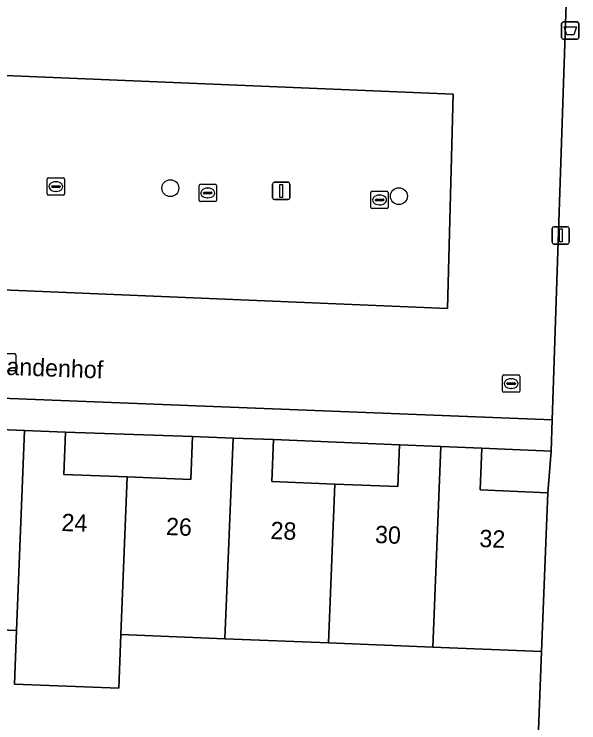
# Model space of a CAD drawing. Extents: x 160786 to 161429, y 386828 to 387485.
# Drawn here: x 161067.25 to 161099.81, y 387170.31 to 387211.19 of the extents above; entities that cross this region are included whole.
import ezdxf

# ---------------------------------------------------------------- set-up
doc = ezdxf.new("R2010")
doc.units = 0
for name, color, linetype in [('IMGEO_Afvalbak', 7, 'Continuous'), ('IMGEO_Boom', 7, 'Continuous'), ('IMGEO_Erf', 7, 'Continuous'), ('IMGEO_Kolk', 7, 'Continuous'), ('IMGEO_Lichtmast', 7, 'Continuous'), ('IMGEO_Openbare_ruimte_label', 7, 'Continuous'), ('IMGEO_Pand', 7, 'Continuous'), ('IMGEO_Pand_nummerreeks', 7, 'Continuous'), ('IMGEO_Parkeervlak_open', 7, 'Continuous'), ('IMGEO_Rijbaan_lokaal_open', 7, 'Continuous'), ('IMGEO_Rioolput', 7, 'Continuous'), ('IMGEO_Voetpad_open', 7, 'Continuous')]:
    doc.layers.add(name, color=color, linetype=linetype)

msp = doc.modelspace()

# ---------------------------------------------------------------- linework, layer by layer
at = {"layer": 'IMGEO_Afvalbak'}
for p, q in [((161098.821, 387209.849), (161098.821, 387210.649)), ((161098.821, 387210.649), (161098.821, 387209.849)), ((161098.921, 387210.749), (161099.711, 387210.749)), ((161099.711, 387210.749), (161098.921, 387210.749)), ((161099.811, 387210.649), (161099.811, 387209.849)), ((161099.811, 387209.849), (161099.811, 387210.649)), ((161099.711, 387209.749), (161098.921, 387209.749)), ((161098.921, 387209.749), (161099.711, 387209.749))]:
    msp.add_line(p, q, dxfattribs=at)
msp.add_lwpolyline([(161098.964, 387210.463), (161099.668, 387210.463), (161099.519, 387209.993), (161099.113, 387209.993), (161098.964, 387210.463)], dxfattribs=at)
for centre, start, end in [((161098.921, 387210.649), 90, 180), ((161098.921, 387210.649), 90, 180), ((161099.711, 387210.649), 0, 90), ((161099.711, 387210.649), 360, 90), ((161098.921, 387209.849), 180, 270), ((161098.921, 387209.849), 180, 270), ((161099.711, 387209.849), 270, 0), ((161099.711, 387209.849), 270, 0)]:
    msp.add_arc(centre, 0.1, start, end, dxfattribs=at)
at = {"layer": 'IMGEO_Boom'}
for centre in [(161076.258, 387201.154), (161089.435, 387200.693)]:
    msp.add_circle(centre, 0.489, dxfattribs=at)
at = {"layer": 'IMGEO_Erf'}
for points in [[(161070.215, 387187.083), (161070.116, 387184.642), (161073.775, 387184.495), (161077.435, 387184.347), (161077.536, 387186.834)], [(161082.211, 387186.646), (161082.113, 387184.227), (161085.748, 387184.08), (161089.381, 387183.934), (161089.478, 387186.343)], [(161094.224, 387186.152), (161094.127, 387183.743), (161098.029, 387183.585), (161098.215, 387185.98)]]:
    msp.add_lwpolyline(points, close=True, dxfattribs=at)
msp.add_lwpolyline([(161097.233, 387163.345), (161097.659, 387174.419), (161091.385, 387174.672), (161085.378, 387174.915), (161079.404, 387175.156), (161073.408, 387175.398), (161073.283, 387172.301), (161067.264, 387172.544), (161067.389, 387175.64), (161061.396, 387175.882), (161055.397, 387176.124), (161049.305, 387176.37), (161043.243, 387176.615), (161042.991, 387170.375), (161039.859, 387170.501), (161040.111, 387176.741), (161037.169, 387176.86), (161031.147, 387177.103), (161025.183, 387177.344), (161019.173, 387177.586), (161013.147, 387177.829), (161007.179, 387178.07), (161001.282, 387178.308), (161000.924, 387167.442)], dxfattribs=at)
at = {"layer": 'IMGEO_Kolk'}
for p, q in [((161069.16, 387200.818), (161069.16, 387201.67)), ((161069.235, 387201.744), (161070.087, 387201.744)), ((161069.648, 387201.524), (161069.673, 387201.524)), ((161070.161, 387201.67), (161070.161, 387200.818)), ((161069.419, 387201.238), (161069.419, 387201.25)), ((161069.857, 387201.201), (161069.459, 387201.201)), ((161069.462, 387201.287), (161069.86, 387201.287)), ((161069.903, 387201.25), (161069.903, 387201.238)), ((161077.913, 387200.451), (161077.913, 387201.303)), ((161077.988, 387201.377), (161078.84, 387201.377)), ((161078.401, 387201.157), (161078.426, 387201.157)), ((161078.914, 387201.303), (161078.914, 387200.451)), ((161070.087, 387200.744), (161069.235, 387200.744)), ((161069.671, 387200.964), (161069.646, 387200.964)), ((161078.172, 387200.871), (161078.172, 387200.883)), ((161078.61, 387200.834), (161078.212, 387200.834)), ((161078.215, 387200.92), (161078.613, 387200.92)), ((161078.656, 387200.883), (161078.656, 387200.871)), ((161087.824, 387200.046), (161087.824, 387200.898)), ((161087.899, 387200.972), (161088.751, 387200.972)), ((161088.312, 387200.752), (161088.337, 387200.752)), ((161088.825, 387200.898), (161088.825, 387200.046)), ((161078.84, 387200.377), (161077.988, 387200.377)), ((161078.424, 387200.597), (161078.399, 387200.597)), ((161088.083, 387200.466), (161088.083, 387200.478)), ((161088.521, 387200.429), (161088.123, 387200.429)), ((161088.126, 387200.515), (161088.524, 387200.515)), ((161088.567, 387200.478), (161088.567, 387200.466)), ((161088.751, 387199.972), (161087.899, 387199.972)), ((161088.335, 387200.192), (161088.31, 387200.192))]:
    msp.add_line(p, q, dxfattribs=at)
for points in [[(161069.16, 387200.818), (161069.16, 387201.67)], [(161069.235, 387201.744), (161070.087, 387201.744)], [(161070.161, 387201.67), (161070.161, 387200.818)], [(161077.913, 387200.451), (161077.913, 387201.303)], [(161077.988, 387201.377), (161078.84, 387201.377)], [(161078.914, 387201.303), (161078.914, 387200.451)], [(161070.087, 387200.744), (161069.235, 387200.744)], [(161087.824, 387200.046), (161087.824, 387200.898)], [(161087.899, 387200.972), (161088.751, 387200.972)], [(161088.825, 387200.898), (161088.825, 387200.046)], [(161078.84, 387200.377), (161077.988, 387200.377)], [(161088.751, 387199.972), (161087.899, 387199.972)]]:
    msp.add_lwpolyline(points, dxfattribs=at)
for centre, radius, start, end in [((161069.237, 387201.668), 0.0765, 91.552, 178.448), ((161069.237, 387201.668), 0.0765, 91.552, 178.448), ((161070.085, 387201.668), 0.0765, 1.552, 88.448), ((161070.085, 387201.668), 0.0765, 1.552, 88.448), ((161069.459, 387201.247), 0.0403, 85.8775, 175.7526), ((161069.456, 387201.237), 0.0366, 178.938, 274.7102), ((161069.86, 387201.244), 0.043, 264.8664, 352.4533), ((161069.864, 387201.249), 0.0386, 1.7309, 96.639), ((161077.99, 387201.301), 0.0765, 91.552, 178.448), ((161077.99, 387201.301), 0.0765, 91.552, 178.448), ((161078.838, 387201.301), 0.0765, 1.552, 88.448), ((161078.838, 387201.301), 0.0765, 1.552, 88.448), ((161069.237, 387200.82), 0.0765, 181.552, 268.448), ((161069.237, 387200.82), 0.0765, 181.552, 268.448), ((161070.085, 387200.82), 0.0765, 271.552, 358.448), ((161070.085, 387200.82), 0.0765, 271.552, 358.448), ((161078.212, 387200.88), 0.0403, 85.8775, 175.7526), ((161078.209, 387200.87), 0.0366, 178.938, 274.7102), ((161078.613, 387200.877), 0.043, 264.8664, 352.4533), ((161078.617, 387200.882), 0.0386, 1.7309, 96.639), ((161087.901, 387200.896), 0.0765, 91.552, 178.448), ((161087.901, 387200.896), 0.0765, 91.552, 178.448), ((161088.749, 387200.896), 0.0765, 1.552, 88.448), ((161088.749, 387200.896), 0.0765, 1.552, 88.448), ((161077.99, 387200.453), 0.0765, 181.552, 268.448), ((161077.99, 387200.453), 0.0765, 181.552, 268.448), ((161078.838, 387200.453), 0.0765, 271.552, 358.448), ((161078.838, 387200.453), 0.0765, 271.552, 358.448), ((161088.123, 387200.475), 0.0403, 85.8775, 175.7526), ((161088.12, 387200.465), 0.0366, 178.938, 274.7102), ((161088.524, 387200.472), 0.043, 264.8664, 352.4533), ((161088.528, 387200.477), 0.0386, 1.7309, 96.639), ((161087.901, 387200.048), 0.0765, 181.552, 268.448), ((161087.901, 387200.048), 0.0765, 181.552, 268.448), ((161088.749, 387200.048), 0.0765, 271.552, 358.448), ((161088.749, 387200.048), 0.0765, 271.552, 358.448)]:
    msp.add_arc(centre, radius, start, end, dxfattribs=at)
for centre, major_axis, ratio, start_param, end_param in [((161069.647, 387201.244), (-0.387, 0.002), 0.722429, 4.712389, 7.853982), ((161069.672, 387201.244), (-0.39, 0.002), 0.717154, 1.570796, 4.712389), ((161078.4, 387200.877), (-0.387, 0.002), 0.722429, 4.712389, 7.853982), ((161078.425, 387200.877), (-0.39, 0.002), 0.717154, 1.570796, 4.712389), ((161088.311, 387200.472), (-0.387, 0.002), 0.722429, 4.712389, 7.853982), ((161088.336, 387200.472), (-0.39, 0.002), 0.717154, 1.570796, 4.712389)]:
    msp.add_ellipse(centre, major_axis=major_axis, ratio=ratio, start_param=start_param, end_param=end_param, dxfattribs=at)
at = {"layer": 'IMGEO_Lichtmast'}
for p, q in [((161082.157, 387200.594), (161082.157, 387201.394)), ((161082.157, 387201.394), (161082.157, 387200.594)), ((161082.257, 387201.494), (161083.047, 387201.494)), ((161083.047, 387201.494), (161082.257, 387201.494)), ((161083.147, 387201.394), (161083.147, 387200.594)), ((161083.147, 387200.594), (161083.147, 387201.394)), ((161083.047, 387200.494), (161082.257, 387200.494)), ((161082.257, 387200.494), (161083.047, 387200.494)), ((161098.272, 387198.03), (161098.272, 387198.83)), ((161098.272, 387198.83), (161098.272, 387198.03)), ((161098.372, 387198.93), (161099.162, 387198.93)), ((161099.162, 387198.93), (161098.372, 387198.93)), ((161099.262, 387198.83), (161099.262, 387198.03)), ((161099.262, 387198.03), (161099.262, 387198.83)), ((161099.162, 387197.93), (161098.372, 387197.93)), ((161098.372, 387197.93), (161099.162, 387197.93))]:
    msp.add_line(p, q, dxfattribs=at)
for points in [[(161082.577, 387201.369), (161082.727, 387201.369), (161082.727, 387200.619), (161082.577, 387200.619), (161082.577, 387201.369)], [(161098.692, 387198.805), (161098.842, 387198.805), (161098.842, 387198.055), (161098.692, 387198.055), (161098.692, 387198.805)]]:
    msp.add_lwpolyline(points, dxfattribs=at)
for centre, start, end in [((161082.257, 387201.394), 90, 180), ((161082.257, 387201.394), 90, 180), ((161083.047, 387201.394), 0, 90), ((161083.047, 387201.394), 360, 90), ((161082.257, 387200.594), 180, 270), ((161082.257, 387200.594), 180, 270), ((161083.047, 387200.594), 270, 0), ((161083.047, 387200.594), 270, 0), ((161098.372, 387198.83), 90, 180), ((161098.372, 387198.83), 90, 180), ((161099.162, 387198.83), 0, 90), ((161099.162, 387198.83), 360, 90), ((161098.372, 387198.03), 180, 270), ((161098.372, 387198.03), 180, 270), ((161099.162, 387198.03), 270, 0), ((161099.162, 387198.03), 270, 0)]:
    msp.add_arc(centre, 0.1, start, end, dxfattribs=at)
at = {"layer": 'IMGEO_Pand'}
for points in [[(161065.496, 387187.273), (161065.397, 387184.815), (161061.762, 387184.962), (161061.396, 387175.882), (161067.389, 387175.64), (161067.855, 387187.178)], [(161073.775, 387184.495), (161070.116, 387184.642), (161070.215, 387187.083), (161067.855, 387187.178), (161067.389, 387175.64), (161067.264, 387172.544), (161073.283, 387172.301), (161073.408, 387175.398)], [(161077.536, 387186.834), (161077.435, 387184.347), (161073.775, 387184.495), (161073.408, 387175.398), (161079.404, 387175.156), (161079.872, 387186.74)], [(161079.872, 387186.74), (161079.404, 387175.156), (161085.378, 387174.915), (161085.748, 387184.08), (161082.113, 387184.227), (161082.211, 387186.646)], [(161089.478, 387186.343), (161089.381, 387183.934), (161085.748, 387184.08), (161085.378, 387174.915), (161091.385, 387174.672), (161091.852, 387186.247)], [(161091.852, 387186.247), (161091.385, 387174.672), (161097.659, 387174.419), (161098.029, 387183.585), (161094.127, 387183.743), (161094.224, 387186.152)]]:
    msp.add_lwpolyline(points, close=True, dxfattribs=at)
at = {"layer": 'IMGEO_Parkeervlak_open'}
msp.add_lwpolyline([(161092.567, 387206.57), (161045.954, 387208.523), (161045.642, 387208.536), (161045.124, 387196.181), (161045.495, 387196.166), (161092.237, 387194.215)], close=True, dxfattribs=at)
at = {"layer": 'IMGEO_Rijbaan_lokaal_open'}
msp.add_lwpolyline([(161032.801, 387190.374), (161098.276, 387187.786), (161099.107, 387212.357)], dxfattribs=at)
msp.add_lwpolyline([(161092.567, 387206.57), (161092.237, 387194.215), (161045.495, 387196.166), (161045.124, 387196.181), (161045.642, 387208.536), (161045.954, 387208.523)], close=True, dxfattribs=at)
at = {"layer": 'IMGEO_Rioolput'}
for p, q in [((161066.416, 387191.612), (161067.268, 387191.612)), ((161067.342, 387191.538), (161067.342, 387190.686)), ((161067.268, 387190.612), (161066.416, 387190.612)), ((161095.41, 387189.452), (161095.41, 387190.304)), ((161095.485, 387190.378), (161096.337, 387190.378)), ((161095.898, 387190.158), (161095.923, 387190.158)), ((161096.411, 387190.304), (161096.411, 387189.452)), ((161095.669, 387189.872), (161095.669, 387189.884)), ((161096.107, 387189.835), (161095.709, 387189.835)), ((161095.712, 387189.921), (161096.11, 387189.921)), ((161096.153, 387189.884), (161096.153, 387189.872)), ((161096.337, 387189.378), (161095.485, 387189.378)), ((161095.921, 387189.598), (161095.896, 387189.598))]:
    msp.add_line(p, q, dxfattribs=at)
for points in [[(161066.416, 387191.612), (161067.268, 387191.612)], [(161067.342, 387191.538), (161067.342, 387190.686)], [(161067.268, 387190.612), (161066.416, 387190.612)], [(161095.41, 387189.452), (161095.41, 387190.304)], [(161095.485, 387190.378), (161096.337, 387190.378)], [(161096.411, 387190.304), (161096.411, 387189.452)], [(161096.337, 387189.378), (161095.485, 387189.378)]]:
    msp.add_lwpolyline(points, dxfattribs=at)
for centre, radius, start, end in [((161067.266, 387191.536), 0.0765, 1.552, 88.448), ((161067.266, 387191.536), 0.0765, 1.552, 88.448), ((161067.266, 387190.688), 0.0765, 271.552, 358.448), ((161067.266, 387190.688), 0.0765, 271.552, 358.448), ((161095.487, 387190.302), 0.0765, 91.552, 178.448), ((161095.487, 387190.302), 0.0765, 91.552, 178.448), ((161096.335, 387190.302), 0.0765, 1.552, 88.448), ((161096.335, 387190.302), 0.0765, 1.552, 88.448), ((161095.709, 387189.881), 0.0403, 85.8775, 175.7526), ((161095.706, 387189.871), 0.0366, 178.938, 274.7102), ((161096.11, 387189.878), 0.043, 264.8664, 352.4533), ((161096.114, 387189.883), 0.0386, 1.7309, 96.639), ((161095.487, 387189.454), 0.0765, 181.552, 268.448), ((161095.487, 387189.454), 0.0765, 181.552, 268.448), ((161096.335, 387189.454), 0.0765, 271.552, 358.448), ((161096.335, 387189.454), 0.0765, 271.552, 358.448)]:
    msp.add_arc(centre, radius, start, end, dxfattribs=at)
for centre, major_axis, ratio, start_param, end_param in [((161095.897, 387189.878), (-0.387, 0.002), 0.722429, 4.712389, 7.853982), ((161095.922, 387189.878), (-0.39, 0.002), 0.717154, 1.570796, 4.712389)]:
    msp.add_ellipse(centre, major_axis=major_axis, ratio=ratio, start_param=start_param, end_param=end_param, dxfattribs=at)
at = {"layer": 'IMGEO_Voetpad_open'}
for points in [[(161096.207, 387257.787), (161096.017, 387252.845), (161096.232, 387252.836), (161096.116, 387250), (161096.065, 387248.737), (161095.755, 387241.593), (161095.585, 387237.429), (161095.453, 387233.674), (161095.334, 387230.294), (161095.165, 387226.125), (161094.876, 387218.902), (161094.616, 387212.509), (161099.107, 387212.357), (161098.276, 387187.786), (161098.215, 387185.98), (161098.029, 387183.585), (161097.659, 387174.419), (161097.233, 387163.345)], [(161031.742, 387189.416), (161031.71, 387188.614), (161033.897, 387188.525), (161041.369, 387188.239), (161043.708, 387188.145), (161046.047, 387188.05), (161053.494, 387187.747), (161055.862, 387187.652), (161058.231, 387187.556), (161065.496, 387187.273), (161067.855, 387187.178), (161070.215, 387187.083), (161077.536, 387186.834), (161079.872, 387186.74), (161082.211, 387186.646), (161089.478, 387186.343), (161091.852, 387186.247), (161094.224, 387186.152), (161098.215, 387185.98), (161098.276, 387187.786), (161032.801, 387190.374)]]:
    msp.add_lwpolyline(points, dxfattribs=at)

# ---------------------------------------------------------------- texts
at = {"layer": 'IMGEO_Openbare_ruimte_label'}
msp.add_text('Viandenhof', height=1, rotation=357.8789, dxfattribs=at).set_placement((161065.605, 387190.423))
at = {"layer": 'IMGEO_Pand_nummerreeks'}
for s, rotation, p in [('24', 357.8056, (161069.97, 387181.378)), ('26', 357.8058, (161075.994, 387181.147)), ('28', 357.8058, (161082.021, 387180.916)), ('30', 357.8058, (161088.045, 387180.685)), ('32', 357.8058, (161094.063, 387180.455))]:
    msp.add_text(s, height=1, rotation=rotation, dxfattribs=at).set_placement(p)

doc.saveas('drawing.dxf')
